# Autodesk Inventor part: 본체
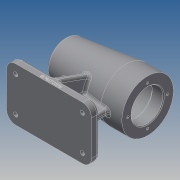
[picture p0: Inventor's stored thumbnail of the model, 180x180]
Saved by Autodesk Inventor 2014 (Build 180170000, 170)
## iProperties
Created: 2018-09
Part Number: 본체
Material: Generic
Document SubType Name: Modeling
Designer: kb542
Density: 1 g/cm^3
Appearance: Default
Author: kb542
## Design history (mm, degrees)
sketch "스케치2"
  geometry: L1 (-56, -35)-(56, -35); L2 (56, -35)-(56, 35); L3 (56, 35)-(-56, 35); L4 (-56, 35)-(-56, -35); L5 (-56, -35)-(56, 35); L6 (56, -35)-(-56, 35); 3 further points
  constraints: 12 end point, 3 midpoint, 2 parallel, 1 coincident, 1 horizontal, 1 perpendicular
  dimensions: "d0" = 112 distance of L2.end L3.end; "d1" = 70 distance between parallel lines of L1 L3
extrude "돌출1" new body sketch "스케치2" distance "d2" = 10; taper "d3" = 0 deg
sketch "스케치5"
  geometry: L1 (-52.27, 98.144)-(28, 108); L2 (28, 108)-(56, 108); L3 (56, 108)-(56, 74); L4 (56, 74)-(-56, 74); L5 (56, 0)-(56, 10) reference; L6 (-56, 0)-(56, 0) reference; A1 r 80 centre (24, 74) between (-52.27, 98.144) and (-56, 74); 1 further point
  constraints: 8 end point, 2 perpendicular, 2 point on circle, 1 centre point, 1 horizontal, 1 point on line
  dimensions: "d4" = 0 distance between parallel lines of L3 L5; "d5" = 28 distance of L1.end L2.end; "d6" = 112 distance from line of L3 L4.end; "d7" = 7 deg angle of L2 L1; "d8" = 80 radius of A1; "d9" = 68 diameter of L2 L4; "d10" = 74 distance between parallel lines of L4 L6
revolve "회전1" sketch "스케치5" stored, may be unused: angle "d11" = 90 deg
sketch "스케치6"
  geometry: L1 (-38, 10)-(-27.436, 49.426); L2 (38, 43.205)-(38, 10); L3 (56, 10)-(-56, 10) reference; L4 (56, 0)-(56, 10) reference; L5 (-56, 0)-(-56, 10) reference; L6 (-56, 10)-(56, 10) reference; L7 (-38, 10)-(38, 10); L8 (-27.436, 49.426)-(38, 43.205); 2 further points
  constraints: 8 end point, 2 point on line, 1 collinear, 1 vertical
  dimensions: "d12" = 18 distance between parallel lines of L4 L2; "d13" = 18 distance from line of L1.start L5; "d14" = 105 deg angle of L1 L3
extrude "돌출2" join sketch "스케치6" stored distance "d15" = 8; taper "d16" = 0 deg
sketch "스케치7"
  geometry: L1 (10, -35)-(0, -35) reference; L2 (0, -35)-(0, 35) reference; L3 (0, 35)-(10, 35) reference; L4 (10, 35)-(10, 4) reference; L5 (10, 4)-(43.701, 4) reference; L6 (43.701, -4)-(10, -4) reference; L7 (10, -4)-(10, -35) reference; L8 (10, 35)-(56.666, 18.015); L9 (10, -35)-(56.666, -18.015); L10 (10, 35)-(10, -35); L11 (10, -35)-(10, 35) reference; L12 (10, -35)-(0, -35) reference; L13 (0, -35)-(0, 35) reference; L14 (0, 35)-(10, 35) reference; L15 (10, 35)-(10, 4) reference; L16 (10, 4)-(43.701, 4) reference; L17 (43.701, -4)-(10, -4) reference; L18 (10, -4)-(10, -35) reference; A1 r 30.562 centre (74, 0) between (43.701, -4) and (43.701, 4) reference; A2 r 30.562 centre (74, 0) between (43.701, -4) and (43.701, 4) reference; A3 r 25 centre (74, 0) between (56.666, 18.015) and (56.666, -18.015); 4 further points
  constraints: 6 end point, 4 point on circle, 2 point on line, 1 centre point, 1 coincident, 1 collinear
  dimensions: "d17" = 110 deg angle of L8 L10; "d18" = 110 deg angle of L9 L7; "d21" = 50 diameter of A3
extrude "돌출5" join sketch "스케치7" stored distance "d24" = 8; taper "d25" = 0 deg
sketch "스케치8"
  geometry: L1 (-56, 74)-(76.223, 74); L2 (-50, 74)-(-50, 84.5); L3 (-50, 84.5)-(-47, 84.5); L4 (-43, 91.5)-(-25, 91.5); L5 (-25, 91.5)-(-25, 95); L6 (-25, 95)-(-13, 95); L7 (-13, 95)-(-13, 98); L8 (-13, 98)-(41, 98); L9 (41, 98)-(41, 95); L10 (41, 95)-(56, 95); L11 (56, 95)-(56, 74); L12 (-43, 91.5)-(-43, 90); L13 (-43, 90)-(-47, 90); L14 (-47, 90)-(-47, 84.5); L15 (56, 0)-(-56, 0) reference; L16 (56, 0)-(56, 10) reference; L17 (56, 40)-(56, 108) reference; 2 further points
  constraints: 28 end point, 9 parallel, 3 perpendicular, 3 point on line, 1 horizontal, 1 midpoint
  dimensions: "d28" = 42 diameter of L10 L1; "d29" = 48 diameter of L8 L1; "d31" = 54 distance between parallel lines of L9 L7; "d32" = 42 diameter of L6 L1; "d33" = 12 distance between parallel lines of L7 L5; "d37" = 3 distance between parallel lines of L14 L2; "d38" = 21 diameter of L3 L1; "d39" = 32 diameter of L13 L1; "d40" = 35 diameter of L4 L1; "d41" = 4 distance between parallel lines of L12 L14; "d42" = 18 distance of L4.start L4.end; "d45" = 0 distance between parallel lines of L16 L11; "d46" = 15 distance of L9.end L10.end
revolve "회전2" sketch "스케치8" stored, may be unused: angle "d47" = 90 deg
sketch "스케치9" dims "d48" = 52
  geometry: C1 r 34 at (0, 0) reference; 3 further points
  constraints: 1 coincident, 1 vertical alignment, 2 other
hole "구멍1" sketch "스케치9" at (0, 26) diameter "d49" = 3.242; stored, may be unused: countersink angle "d53" = 90 deg, drill point angle "d55" = 118 deg; dims "d50" = 8, "d51" = 4, "d52" = 2, "d54" = 11
fillet "모깎기1" dims "d59" = 12
hole "구멍2" diameter "d62" = 5.5; stored, may be unused: countersink angle "d66" = 90 deg, drill point angle "d68" = 118 deg; dims "d60" = 10, "d61" = 10, "d63" = 8, "d64" = 9.5, "d65" = 5.4, "d67" = 11
fillet "모깎기2" dims "d69" = 3
fillet "모깎기3" dims "d70" = 3
fillet "모깎기4" dims "d71" = 3
fillet "모깎기5" dims "d72" = 3
fillet "모깎기6" dims "d73" = 3
fillet "모깎기7" dims "d74" = 0.3
fillet "모깎기8" dims "d75" = 3
fillet "모깎기9" dims "d76" = 3
chamfer "모따기1" distance "d77" = 1; stored, may be unused: second distance "d78" = 2, angle "d79" = 45 deg
sketch "스케치10"
  geometry: L1 (0, 0)-(88, 0) reference; L2 (100, 0)-(100, 7) reference; 2 further points
  constraints: 1 other
  dimensions: "d80" = 56 distance from line of point (44, 3) L2; "d81" = 3 distance from line of L1 point (44, 3)
feature "엠보싱1" sketch "스케치10" dims "d0" = 112, "d1" = 70, "d82" = 0.5, "d83" = 0
node "솔리드1"
pattern_circular "원형 패턴1" dims angle "d57" = 360 deg
mirror "대칭1"
mirror "대칭2"
node "절단 모서리 투영1"
node "절단 모서리 투영2"
